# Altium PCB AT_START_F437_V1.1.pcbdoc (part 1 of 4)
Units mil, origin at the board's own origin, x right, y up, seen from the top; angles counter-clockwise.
Board outline 10746.75 x 3533.35 mil, 2 copper layers (Top Layer, Bottom Layer); 198 components, 235 nets, 885 pads, 1100 vias.
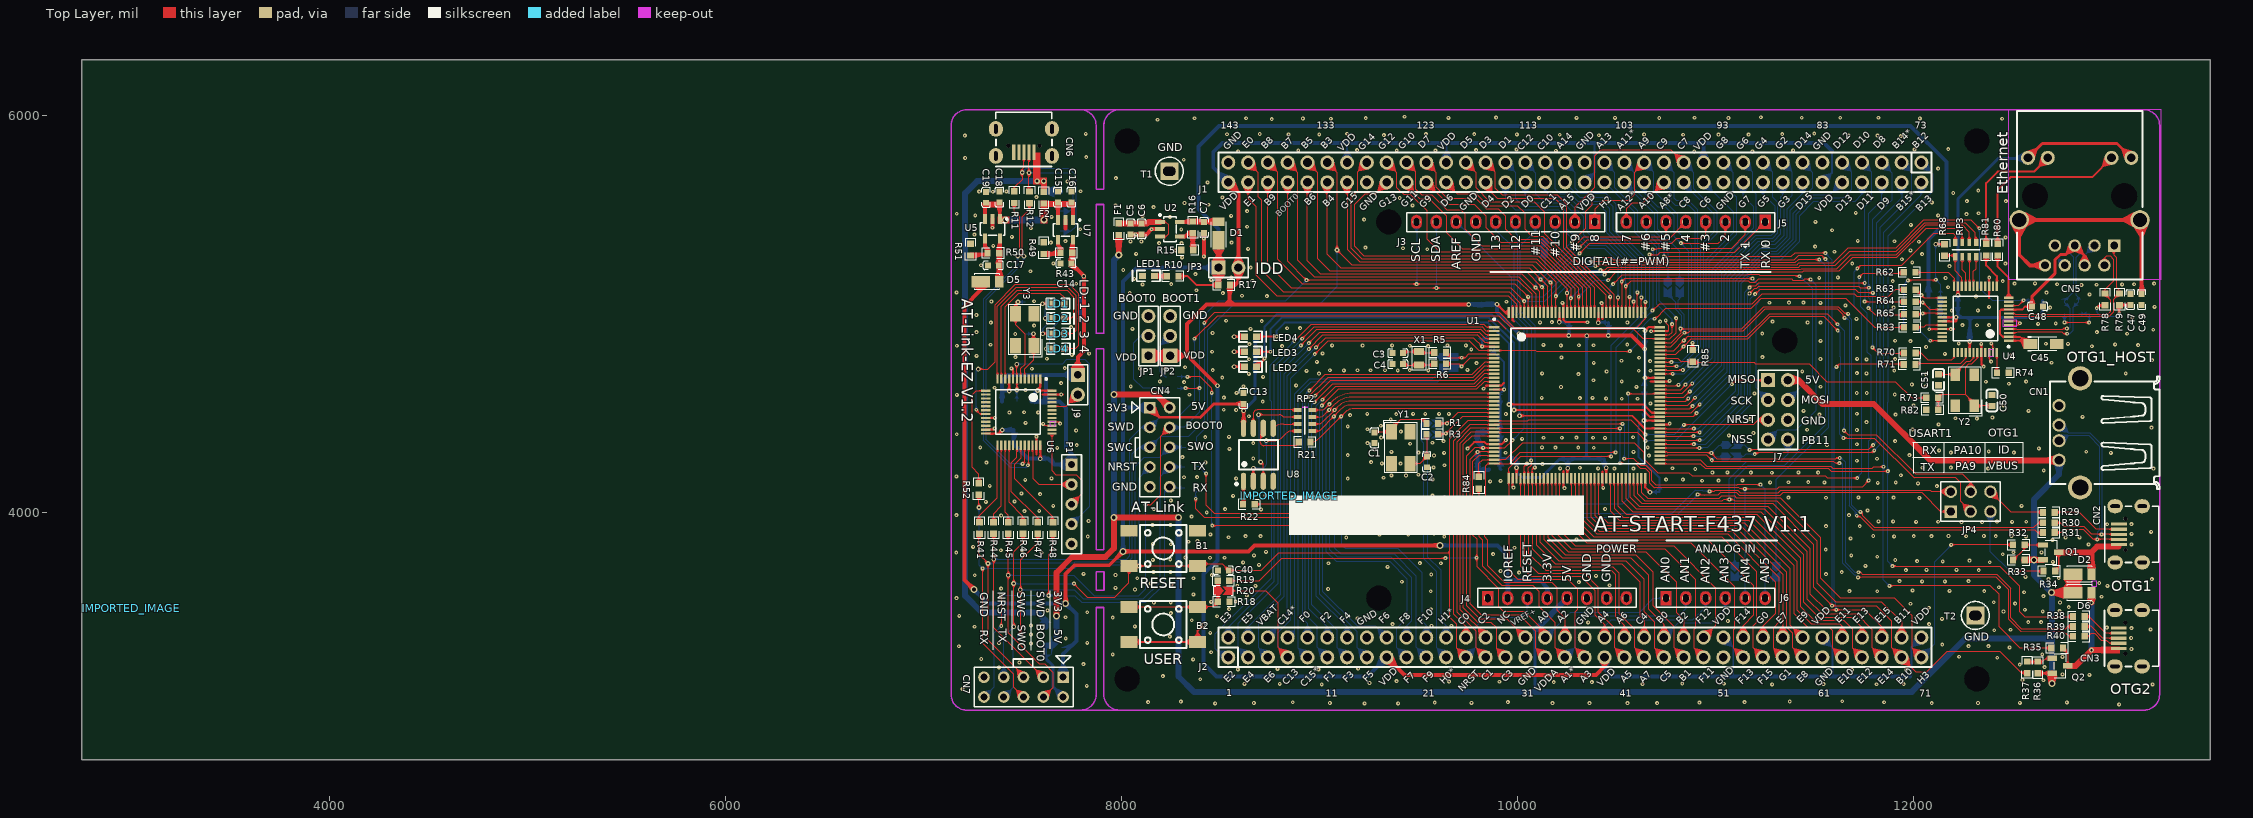
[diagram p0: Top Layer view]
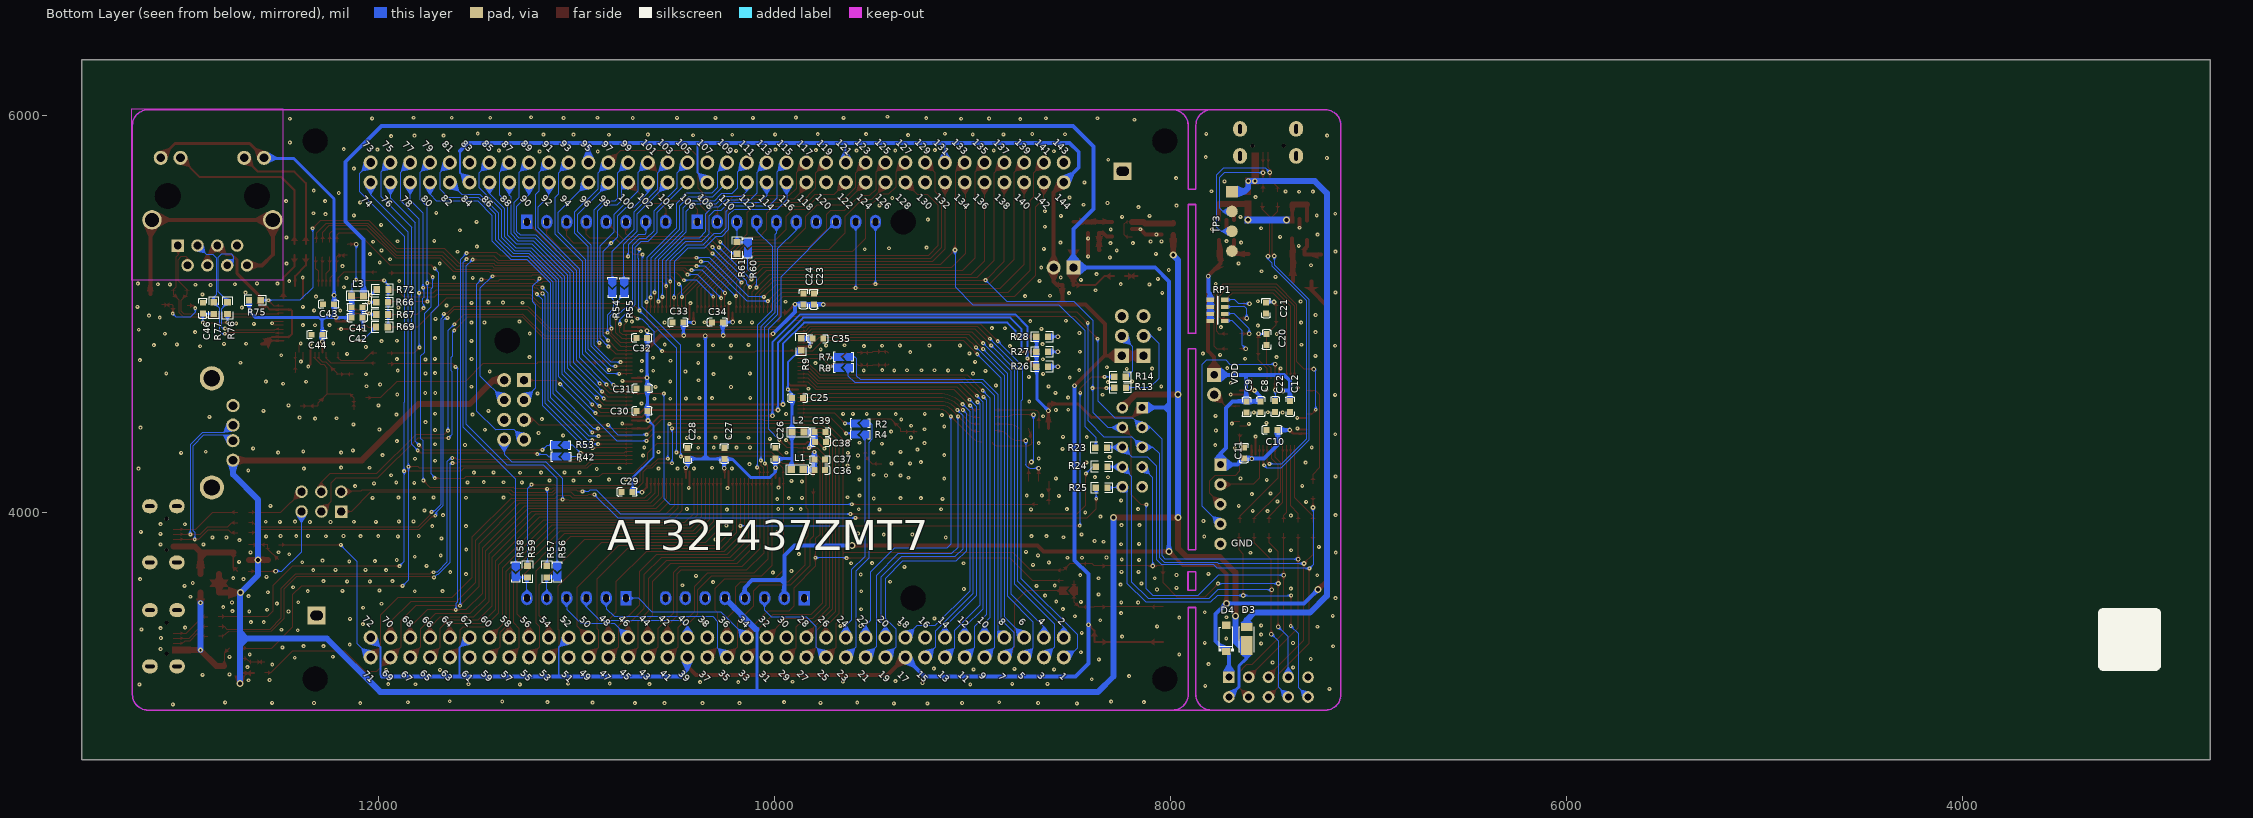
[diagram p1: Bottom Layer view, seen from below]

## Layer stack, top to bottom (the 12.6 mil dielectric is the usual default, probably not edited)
Top Layer: signal copper (thickness not stored)
Dielectric: dielectric 12.6, FR-4, Dk 4.8
Bottom Layer: signal copper (thickness not stored)

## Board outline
13496.75,2750 2750,2750 2750,6283.35 13496.75,6283.35
cut-out: 11412.34,4865.35 ccw(c11349.35,4865.35) 11286.36,4865.35 ccw(c11349.35,4865.35)
cut-out: 9412.34,5465.35 ccw(c9349.35,5465.35) 9286.36,5465.35 ccw(c9349.35,5465.35)
cut-out: 9362.34,3565.36 ccw(c9299.35,3565.36) 9236.36,3565.36 ccw(c9299.35,3565.36)
cut-out: 8090.92,5874.02 ccw(c8027.93,5874.02) 7964.94,5874.02 ccw(c8027.93,5874.02)
cut-out: 8090.92,3157.47 ccw(c8027.93,3157.47) 7964.94,3157.47 ccw(c8027.93,3157.47)
cut-out: 12382.26,3157.47 ccw(c12319.27,3157.47) 12256.28,3157.47 ccw(c12319.27,3157.47)
cut-out: 12382.26,5874.02 ccw(c12319.27,5874.02) 12256.28,5874.02 ccw(c12319.27,5874.02)

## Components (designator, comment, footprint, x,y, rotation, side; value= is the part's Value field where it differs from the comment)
B1 "贴片按键6*6*5 黑色" SW-SMD_4P-L6.0-W6.0-P4.50-LS9.0 8210.8,3816.36 r180 top
B2 "贴片按键6*6*5 红色" SW-SMD_4P-L6.0-W6.0-P4.50-LS9.0 8210.8,3432.36 r180 top
C1 "22pF" 0603_C-M 9277.75,4375.35 r270 top
C2 "22pF" 0603_C-M 9541.37,4253.71 r270 top
C3 "10pF" 0603_C-M 9394.6,4802.55 r180 top
C4 "10pF" 0603_C-M 9394.61,4747 r180 top
C5 "10uF" 0603_C-M 8045.76,5429 r90 top
C6 "0.1uF" 0603_C-M 8100.76,5429 r90 top
C7 "10uF" 0603_C-M 8415.75,5437.35 r90 top
C8 "4.7uF" 0603_C-M 7544.2,4531.56 r90 bottom
C9 "0.1uF" 0603_C-M 7616.2,4530.56 r90 bottom
C10 "0.1uF" 0603_C-M 7487.2,4414.56 r180 bottom
C11 "0.1uF" 0603_C-M 7629.2,4298.56 r270 bottom
C12 "0.1uF" 0603_C-M 7396.2,4532.56 r90 bottom
C13 "0.1uF" 0603_C-M 8615.73,4574.23 r270 top
C14 "10uF" 0603_C-M 7719.11,5255 r0 top
C15 "10uF" 0603_C-M 7678.2,5590.56 r270 top
C16 "0.1uF" 0603_C-M 7747.2,5590.56 r270 top
C17 "10uF" 0603_C-M 7352.2,5245.56 r0 top
C18 "10uF" 0603_C-M 7383.2,5590.56 r270 top
C19 "0.1uF" 0603_C-M 7316.2,5589.56 r270 top
C20 "22pF" 0603_C-M 7514.2,4870.56 r90 bottom
C21 "22pF" 0603_C-M 7517.2,5030.56 r270 bottom
C22 "0.1uF" 0603_C-M 7471.2,4532.56 r90 bottom
C23 "4.7uF" 0603_C-M 9800.75,5075.35 r270 bottom
C24 "0.1uF" 0603_C-M 9852.75,5076.35 r270 bottom
C25 "0.1uF" 0603_C-M 9882.75,4576.35 r0 bottom
C26 "0.1uF" 0603_C-M 9994.75,4297.35 r270 bottom
C27 "0.1uF" 0603_C-M 10252.75,4295.35 r270 bottom
C28 "0.1uF" 0603_C-M 10437.75,4296.35 r270 bottom
C29 "0.1uF" 0603_C-M 10743.75,4101.35 r180 bottom
C30 "0.1uF" 0603_C-M 10668.75,4510.35 r180 bottom
C31 "0.1uF" 0603_C-M 10667.75,4623.35 r180 bottom
C32 "0.1uF" 0603_C-M 10669.75,4879.35 r180 bottom
C33 "0.1uF" 0603_C-M 10486.75,4957.35 r180 bottom
C34 "0.1uF" 0603_C-M 10287.75,4958.35 r180 bottom
C35 "0.1uF" 0603_C-M 9780.75,4875.35 r0 bottom
C36 "1uF" 0603_C-M 9770.75,4212.35 r0 bottom
C37 "0.1uF" 0603_C-M 9770.75,4264.35 r0 bottom
C38 "0.1uF" 0603_C-M 9767.75,4354.35 r0 bottom
C39 "1uF" 0603_C-M 9768.75,4404.35 r0 bottom
C40 "0.1uF" 0603_C-M 8513.75,3705.35 r0 top
C41 "10uF" 0603_C-M 12106.75,5034.35 r0 bottom
C42 "0.1uF" 0603_C-M 12106.75,4982.35 r0 bottom
C43 "0.1uF" 0603_C-M 12250.75,5049.35 r180 bottom
C44 "0.1uF" 0603_C-M 12309.75,4895.35 r180 bottom
C45 "47uF" CAP-SMD_L3.2-W1.6-R-RD 12655.75,4849.35 r180 top
C46 "0.1uF" 0603_C-M 12886.04,5029.49 r270 bottom
C47 "0.1uF" 0603_C-M 13094.07,5073.23 r270 top
C48 "0.1uF" 0603_C-M 12625.75,5037.35 r0 top
C49 "0.1uF" 0603_C-M 13151.2,5073.23 r270 top
C50 "0603CG300J500NT" C0603 12395.11,4563.79 r90 top
C51 "0603CG300J500NT" C0603 12125.62,4668.2 r270 top
CN1 "JTJ-USB-AF-08" USB-A-TH__USB-AF-90 12787.14,4399.88 r90 top
CN2 "USB_micro B" USB_MIC_DIP 13036.55,3887.68 r0 top
CN3 "USB_micro B" USB_MIC_DIP 13035.76,3362.87 r0 top
CN4 "CON10A_0" HDR2X5 8142.77,4527.36 r270 top
CN5 "RJ45(TRJ201)" RJ45-TH_HR911105A 12837.8,5517.32 r180 top
CN6 "USB_micro B" USB_MIC_DIP 7506.75,5817.58 r90 top
CN7 "CON1" HDR2X5 7705,3165.97 r180 top
D1 "DFLS130L-7" POWERDI-123_L2.8-W1.8-LS3.7-RD 8489.75,5419.36 r90 top
D2 "DFLS130L-7" POWERDI-123_L2.8-W1.8-LS3.7-RD 12850.97,3686.74 r0 top
D3 "DFLS130L-7" POWERDI-123_L2.8-W1.8-LS3.7-RD 7615.25,3372.57 r90 bottom
D4 "SMF3.3A" SOD-123_L2.8-W1.8-LS3.7-RD 7718.2,3362.57 r90 bottom
D5 "DFLS130L-7" POWERDI-123_L2.8-W1.8-LS3.7-RD 7335.25,5163.56 r0 top
D6 "DFLS130L-7" POWERDI-123_L2.8-W1.8-LS3.7-RD 12850.97,3592.97 r0 top
F1 "SMD0603B050TF" R0603 7985.8,5428.97 r90 top
F2 "SMD0603B050TF" R0603 7607.2,5587.56 r270 top
IMPORTED_IMAGE "IMPORTED_IMAGE" IMPORTED_IMAGE 3000,3514.32 r0 top
IMPORTED_IMAGE "IMPORTED_IMAGE" IMPORTED_IMAGE 8845.96,4083.03 r0 top
J1 "HDR 2X36" HDR_2.54_2X36 10288.72,5715.04 r180 top
J2 "HDR 2X36" HDR_2.54_2X36 10288.72,3316.46 r0 top
J3 "CON10" "FEMALE HEADER 1X10" 9939.35,5465.35 r0 top
J4 "CON8" "FEMALE HEADER 1X8" 10199.35,3565.35 r0 top
J5 "CON8" "FEMALE HEADER 1X8" 10899.35,5465.35 r180 top
J6 "CON6" "FEMALE HEADER 1X6" 10999.35,3565.35 r0 top
J7 "Header 4X2" HDR2X4 11264.35,4665.94 r270 top
J9 "1X2P,Male,DIP_2.54" HDR1X2 7779,4692.97 r270 top
JP1 "Jumper 1x3P" "HEADER 1X3" 8135.76,4789.35 r90 top
JP2 "Jumper 1x3P" "HEADER 1X3" 8245.75,4789.35 r90 top
JP3 "Jumper 1x2P" "HEADER 1X2" 8489.75,5234.35 r0 top
JP4 "Header 3X2" HDR2X3 12187.48,4002.73 r0 top
L1 "0.5A,600Ω@100Mhz" 0603_L 9884.8,4214.36 r180 bottom
L2 "0.5A,600Ω@100Mhz" 0603_L 9880.8,4403.36 r180 bottom
L3 "0.5A,600Ω@100Mhz" 0603_L 12104.8,5091.36 r0 bottom
LD1 "RED" LED0603 7649.02,5051.81 r0 top
LD2 "GREEN" LED0603 7649.98,4977.72 r0 top
LD3 "BLUE" LED0603 7650.02,4900.81 r0 top
LD4 "YELLOW" LED0603 7649.98,4824.81 r0 top
LED1 "RED" LED0603 8165.76,5192.35 r180 top
LED2 "RED" LED0603 8620.59,4734.39 r0 top
LED3 "YELLOW" LED0603 8620.6,4809.37 r0 top
LED4 "GREEN" LED0603 8620.6,4885.67 r0 top
P1 "HDR-M-2.54_1x5" HDR-M-2.54_1X5 7747.7,4039.57 r270 top
Q1 "SI2301" SOT-23-3_L2.9-W1.3-P1.90-LS2.4-BR 12692.6,3796.36 r180 top
Q2 "SI2301" SOT-23-3_L2.9-W1.3-P1.90-LS2.4-BR 12738.7,3223.57 r180 top
R1 "0603WAF0000T5E" R0603 9569.75,4447.35 r0 top
R2 "NC" SB-PAD 9567.75,4447.35 r0 bottom
R3 "0603WAF0000T5E" R0603 9569.75,4393.35 r0 top
R4 "NC" SB-PAD 9567.75,4391.35 r0 bottom
R5 "0603WAF0000T5E" R0603 9608.75,4805.31 r0 top
R6 "0603WAF0000T5E" R0603 9608.75,4748.57 r0 top
R7 "NC" SB-PAD 9651.75,4783.35 r0 bottom
R8 "NC" SB-PAD 9651.75,4729.35 r0 bottom
R9 "0603WAF0000T5E" R0603 9864.75,4847.35 r270 bottom
R10 "0603WAF1001T5E" R0603 8257.8,5191.36 r180 top
R11 "0603WAF0000T5E" R0603 7458.2,5590.56 r270 top
R12 "0603WAF0000T5E" R0603 7535.2,5589.56 r270 top
R13 "0603WAF1002T5E" R0603 8253.75,4627.35 r0 bottom
R14 "0603WAF1002T5E" R0603 8254.75,4683.35 r0 bottom
R15 "0603WAF1502T5E" R0603 8331.75,5323.35 r180 top
R16 "0603WAF5102T5E" R0603 8359.75,5437.35 r90 top
R17 "0603WAF0000T5E" R0603 8517.75,5146.35 r0 top
R18 "0603WAF1003T5E" R0603 8515.75,3547.35 r180 top
R19 "0603WAF0000T5E" R0603 8514.75,3653.35 r0 top
R20 "NC" SB-PAD 8514.75,3602.35 r0 top
R21 "0603WAF330JT5E" R0603 8924.73,4353.23 r180 top
R22 "0603WAF330JT5E" R0603 8643.05,4039.37 r180 top
R23 "0603WAF4700T5E" R0603 8349.8,4325.36 r0 bottom
R24 "0603WAF4700T5E" R0603 8347.8,4229.36 r0 bottom
R25 "0603WAF4700T5E" R0603 8347.2,4122.47 r0 bottom
R26 "0603WAF1001T5E" R0603 8647.4,4734.39 r180 bottom
R27 "0603WAF1001T5E" R0603 8647.4,4809.38 r180 bottom
R28 "0603WAF1001T5E" R0603 8647.4,4885.68 r180 bottom
R29 "0603WAF1001T5E" R0603 12682.57,3998.35 r0 top
R30 "0603WAF220JT5E" R0603 12682.57,3946.35 r0 top
R31 "0603WAF220JT5E" R0603 12682.57,3896.35 r0 top
R32 "0603WAF4700T5E" R0603 12530.57,3834.35 r0 top
R33 "0603WAF1002T5E" R0603 12530.57,3758.35 r0 top
R34 "0603WAF1002T5E" R0603 12684.6,3702.36 r0 top
R35 "0603WAF1002T5E" R0603 12724.7,3313.57 r0 top
R36 "0603WAF1002T5E" R0603 12626.72,3215.58 r270 top
R37 "0603WAF4700T5E" R0603 12572.72,3215.58 r90 top
R38 "0603WAF1001T5E" R0603 12834.51,3472.35 r0 top
R39 "0603WAF220JT5E" R0603 12834.51,3422.35 r0 top
R40 "0603WAF220JT5E" R0603 12834.51,3372.35 r0 top
R41 "0603WAF330JT5E" R0603 7283.2,3919.56 r90 top
R42 "NC" SB-PAD 11078.75,4280.35 r0 bottom
R43 "0603WAF4702T5E" R0603 7721.2,5309.93 r0 top
R44 "0603WAF330JT5E" R0603 7353.2,3919.57 r90 top
R45 "0603WAF330JT5E" R0603 7428.2,3919.57 r90 top
R46 "0603WAF330JT5E" R0603 7502.2,3919.56 r90 top
R47 "0603WAF330JT5E" R0603 7577.2,3919.57 r90 top
R48 "0603WAF330JT5E" R0603 7653.2,3919.56 r90 top
R49 "0603WAF1502T5E" R0603 7607.2,5332.56 r90 top
R50 "0603WAF5102T5E" R0603 7352.2,5307.56 r0 top
R51 "0603WAF1502T5E" R0603 7237.2,5325.56 r90 top
R52 "0603WAF330JT5E" R0603 7278.2,4116.56 r90 top
R53 "NC" SB-PAD 11080.75,4338.35 r0 bottom
R54 "NC" SB-PAD 10818.94,5134.93 r270 bottom
R55 "NC" SB-PAD 10758.57,5134.14 r270 bottom
R56 "NC" SB-PAD 11095.75,3699.35 r270 bottom
R57 "0603WAF0000T5E" R0603 11149.75,3699.35 r270 bottom
R58 "NC" SB-PAD 11306.49,3698.56 r270 bottom
R59 "0603WAF0000T5E" R0603 11246.6,3699.35 r270 bottom
R60 "NC" SB-PAD 10133.39,5334.56 r270 bottom
R61 "0603WAF0000T5E" R0603 10188.75,5334.35 r90 bottom
R62 "0603WAF330JT5E" R0603 11979.75,5211.35 r0 top
R63 "0603WAF330JT5E" R0603 11980.63,5123.27 r0 top
R64 "0603WAF330JT5E" R0603 11980.63,5062.2 r0 top
R65 "0603WAF330JT5E" R0603 11980.63,4998.37 r0 top
R66 "0603WAF4701T5E" R0603 11980.4,5059.71 r0 bottom
R67 "0603WAF4701T5E" R0603 11981.02,4997.97 r0 bottom
R68 "0603WAF4701T5E" R0603 12155.75,5323.35 r270 top
R69 "0603WAF4701T5E" R0603 11981.41,4934.54 r0 bottom
R70 "0603WAF330JT5E" R0603 11980.4,4803.71 r0 top
R71 "0603WAF330JT5E" R0603 11979.75,4745.35 r0 top
R72 "0603WAF1501T5E" R0603 11978.66,5123.66 r180 bottom
R73 "0603WAF330JT5E" R0603 12093.7,4577.58 r0 top
R74 "0603WAF6801T5E" R0603 12449.75,4703.35 r180 top
R75 "0603WAF4701T5E" R0603 12622.8,5069.36 r0 bottom
R76 "0603WAF499JT5E" R0603 12761.75,5029.35 r90 bottom
R77 "0603WAF499JT5E" R0603 12831.27,5030.28 r90 bottom
R78 "0603WAF499JT5E" R0603 12965.63,5073.62 r90 top
R79 "0603WAF499JT5E" R0603 13038.91,5073.62 r90 top
R80 "0603WAF4700T5E" R0603 12423.75,5325.35 r270 top
R81 "0603WAF4700T5E" R0603 12365.75,5325.35 r270 top
R82 "0603WAF1003T5E" R0603 12093.7,4516.51 r180 top
R83 "0603WAF330JT5E" R0603 11980.63,4932.96 r0 top
R84 "0603WAF0000T5E" R0603 9804.17,4148.12 r90 top
R85 "0603WAF0000T5E" R0603 10884.91,4788.37 r270 top
RP1 "1K" 0603*4,8P4R 7798.2,5071.56 r270 bottom
RP2 "33R" 0603*4,8P4R 8962.73,4409.23 r90 top
RP3 "33R" 0603*4,8P4R 12315.75,5361.35 r180 top
T1 "TESTPOINT TP-5006" TESTHOOK 8241.01,5721.13 r0 top
T2 "TESTPOINT TP-5006" TESTHOOK 12311.19,3477.92 r0 top
TP3 "1X4P_2.54F" "HDR1X4 - TOP" 7689.55,5618.02 r90 bottom
U1 "AT32F437ZMT7" LQFP144_20*20 10299.74,4589.37 r0 top
U2 "RT9080N-08GJ5" SOT-23-5 8258.75,5365.35 r0 top
U4 "DM9162EP" LQFP48_7*7 12311.75,4973.35 r180 top
U5 "RT9080N-08GJ5" SOT-23-5 7285.2,5415.56 r270 top
U6 "AT32F403CGT6" "LQFP48 - 2" 7589.72,4672.02 r270 top
U7 "RT9080N-08GJ5" SOT-23-5 7653.98,5409.91 r270 top
U8 "EN25QH128A-104HIP" SOIC-8_208MIL 8690.7,4289.16 r0 top
X1 "32.768KHz" FC-12M_L2.0-W1.2 9501.97,4776.55 r90 top
Y1 "8MHz" OSC-SMD_4P-L5.0-W3.2-BL 9409.8,4325.36 r270 top
Y2 "X503225MSB4SI" CRYSTAL-SMD_4P-L5.0-W3.2-BL 12257.61,4614.61 r90 top
Y3 "8MHz" OSC-SMD_4P-L5.0-W3.2-BL 7510.6,4920.97 r90 top

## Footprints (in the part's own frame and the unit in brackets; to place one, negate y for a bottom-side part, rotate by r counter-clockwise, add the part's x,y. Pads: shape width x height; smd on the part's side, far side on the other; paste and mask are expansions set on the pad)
0603*4,8P4R [mm]
  rect 0.55x0.95 smd: 1(0,0) 4(2.7,0) 5(2.7,1.85) 8(0,1.85)
  rect 0.5x0.95 smd: 2(0.9,0) 3(1.8,0) 6(1.8,1.85) 7(0.9,1.85)
  silkscreen extent -0.43,0.94 3.1,0.94
0603_C-M [mil]
  rect 30x30 smd: 1(27.5,0) 2(-27.5,0)
  silkscreen extent -50,-21 50,21
0603_L [mm]
  rect 0.93x0.9 smd: 1(-0.77,0) 2(0.77,0)
  silkscreen extent -1.4,-0.64 1.4,0.64
C0603 [mm]
  rect 0.8x0.9 smd: 1(-0.7,0) 2(0.7,0)
  silkscreen extent -1.41,-0.71 1.39,0.72
CAP-SMD_L3.2-W1.6-R-RD [mil]
  rect 69.19x51.02 smd: 1(66.38,0) 2(-66.39,0)
  silkscreen extent -66,-37 81,37
CRYSTAL-SMD_4P-L5.0-W3.2-BL [mm]
  rect 1.6x1.2 smd: 1(-2,-1.2) 2(2,-1.2) 3(2,1.2) 4(-2,1.2)
  silkscreen extent -3.26,-2.26 3.03,2.03
FC-12M_L2.0-W1.2 [mm]
  rect 0.925x1.3 smd: 1(-0.863,0) 2(0.863,0)
  silkscreen extent -1.55,-0.88 1.55,0.88
"FEMALE HEADER 1X6" [mm]
  oval 1x0.7 hole 0.7 slot 1 at 90 deg: 1(-6.35,0) 2(-3.81,0) 3(-1.27,0) 4(1.27,0) 5(3.81,0) 6(6.35,0)
  Top Layer region: 7.05,-0.2 6.956,-0.55 6.7,-0.806 6.35,-0.9 6,-0.806 5.744,-0.55 5.65,-0.2 5.65,0.2 5.744,0.55 6,0.806 6.35,0.9 6.7,0.806 6.956,0.55 7.05,0.2
  Top Layer region: 4.51,-0.2 4.416,-0.55 4.16,-0.806 3.81,-0.9 3.46,-0.806 3.204,-0.55 3.11,-0.2 3.11,0.2 3.204,0.55 3.46,0.806 3.81,0.9 4.16,0.806 4.416,0.55 4.51,0.2
  Top Layer region: 1.97,-0.2 1.876,-0.55 1.62,-0.806 1.27,-0.9 0.92,-0.806 0.664,-0.55 0.57,-0.2 0.57,0.2 0.664,0.55 0.92,0.806 1.27,0.9 1.62,0.806 1.876,0.55 1.97,0.2
  Top Layer region: -0.57,-0.2 -0.664,-0.55 -0.92,-0.806 -1.27,-0.9 -1.62,-0.806 -1.876,-0.55 -1.97,-0.2 -1.97,0.2 -1.876,0.55 -1.62,0.806 -1.27,0.9 -0.92,0.806 -0.664,0.55 -0.57,0.2
  Top Layer region: -3.11,-0.2 -3.204,-0.55 -3.46,-0.806 -3.81,-0.9 -4.16,-0.806 -4.416,-0.55 -4.51,-0.2 -4.51,0.2 -4.416,0.55 -4.16,0.806 -3.81,0.9 -3.46,0.806 -3.204,0.55 -3.11,0.2
  Top Layer region: -7.05,0.9 -5.65,0.9 -5.65,-0.9 -7.05,-0.9
  Bottom Layer region: 7.05,-0.2 6.956,-0.55 6.7,-0.806 6.35,-0.9 6,-0.806 5.744,-0.55 5.65,-0.2 5.65,0.2 5.744,0.55 6,0.806 6.35,0.9 6.7,0.806 6.956,0.55 7.05,0.2
  Bottom Layer region: 4.51,-0.2 4.416,-0.55 4.16,-0.806 3.81,-0.9 3.46,-0.806 3.204,-0.55 3.11,-0.2 3.11,0.2 3.204,0.55 3.46,0.806 3.81,0.9 4.16,0.806 4.416,0.55 4.51,0.2
  Bottom Layer region: 1.97,-0.2 1.876,-0.55 1.62,-0.806 1.27,-0.9 0.92,-0.806 0.664,-0.55 0.57,-0.2 0.57,0.2 0.664,0.55 0.92,0.806 1.27,0.9 1.62,0.806 1.876,0.55 1.97,0.2
  Bottom Layer region: -0.57,-0.2 -0.664,-0.55 -0.92,-0.806 -1.27,-0.9 -1.62,-0.806 -1.876,-0.55 -1.97,-0.2 -1.97,0.2 -1.876,0.55 -1.62,0.806 -1.27,0.9 -0.92,0.806 -0.664,0.55 -0.57,0.2
  Bottom Layer region: -3.11,-0.2 -3.204,-0.55 -3.46,-0.806 -3.81,-0.9 -4.16,-0.806 -4.416,-0.55 -4.51,-0.2 -4.51,0.2 -4.416,0.55 -4.16,0.806 -3.81,0.9 -3.46,0.806 -3.204,0.55 -3.11,0.2
  Bottom Layer region: -7.05,0.9 -5.65,0.9 -5.65,-0.9 -7.05,-0.9
  Multi-Layer region: 7.05,-0.2 6.956,-0.55 6.7,-0.806 6.35,-0.9 6,-0.806 5.744,-0.55 5.65,-0.2 5.65,0.2 5.744,0.55 6,0.806 6.35,0.9 6.7,0.806 6.956,0.55 7.05,0.2
  Multi-Layer region: 4.51,-0.2 4.416,-0.55 4.16,-0.806 3.81,-0.9 3.46,-0.806 3.204,-0.55 3.11,-0.2 3.11,0.2 3.204,0.55 3.46,0.806 3.81,0.9 4.16,0.806 4.416,0.55 4.51,0.2
  Multi-Layer region: 1.97,-0.2 1.876,-0.55 1.62,-0.806 1.27,-0.9 0.92,-0.806 0.664,-0.55 0.57,-0.2 0.57,0.2 0.664,0.55 0.92,0.806 1.27,0.9 1.62,0.806 1.876,0.55 1.97,0.2
  Multi-Layer region: -0.57,-0.2 -0.664,-0.55 -0.92,-0.806 -1.27,-0.9 -1.62,-0.806 -1.876,-0.55 -1.97,-0.2 -1.97,0.2 -1.876,0.55 -1.62,0.806 -1.27,0.9 -0.92,0.806 -0.664,0.55 -0.57,0.2
  Multi-Layer region: -3.11,-0.2 -3.204,-0.55 -3.46,-0.806 -3.81,-0.9 -4.16,-0.806 -4.416,-0.55 -4.51,-0.2 -4.51,0.2 -4.416,0.55 -4.16,0.806 -3.81,0.9 -3.46,0.806 -3.204,0.55 -3.11,0.2
  Multi-Layer region: -7.05,0.9 -5.65,0.9 -5.65,-0.9 -7.05,-0.9
  silkscreen extent -7.62,-1.17 7.62,1.27
"FEMALE HEADER 1X8" [mm]
  oval 1x0.7 hole 0.7 slot 1 at 90 deg: 1(-8.89,0) 2(-6.35,0) 3(-3.81,0) 4(-1.27,0) 5(1.27,0) 6(3.81,0) 7(6.35,0) 8(8.89,0)
  Top Layer region: 9.59,-0.2 9.496,-0.55 9.24,-0.806 8.89,-0.9 8.54,-0.806 8.284,-0.55 8.19,-0.2 8.19,0.2 8.284,0.55 8.54,0.806 8.89,0.9 9.24,0.806 9.496,0.55 9.59,0.2
  Top Layer region: 7.05,-0.2 6.956,-0.55 6.7,-0.806 6.35,-0.9 6,-0.806 5.744,-0.55 5.65,-0.2 5.65,0.2 5.744,0.55 6,0.806 6.35,0.9 6.7,0.806 6.956,0.55 7.05,0.2
  Top Layer region: 4.51,-0.2 4.416,-0.55 4.16,-0.806 3.81,-0.9 3.46,-0.806 3.204,-0.55 3.11,-0.2 3.11,0.2 3.204,0.55 3.46,0.806 3.81,0.9 4.16,0.806 4.416,0.55 4.51,0.2
  Top Layer region: 1.97,-0.2 1.876,-0.55 1.62,-0.806 1.27,-0.9 0.92,-0.806 0.664,-0.55 0.57,-0.2 0.57,0.2 0.664,0.55 0.92,0.806 1.27,0.9 1.62,0.806 1.876,0.55 1.97,0.2
  Top Layer region: -0.57,-0.2 -0.664,-0.55 -0.92,-0.806 -1.27,-0.9 -1.62,-0.806 -1.876,-0.55 -1.97,-0.2 -1.97,0.2 -1.876,0.55 -1.62,0.806 -1.27,0.9 -0.92,0.806 -0.664,0.55 -0.57,0.2
  Top Layer region: -3.11,-0.2 -3.204,-0.55 -3.46,-0.806 -3.81,-0.9 -4.16,-0.806 -4.416,-0.55 -4.51,-0.2 -4.51,0.2 -4.416,0.55 -4.16,0.806 -3.81,0.9 -3.46,0.806 -3.204,0.55 -3.11,0.2
  Top Layer region: -5.65,-0.2 -5.744,-0.55 -6,-0.806 -6.35,-0.9 -6.7,-0.806 -6.956,-0.55 -7.05,-0.2 -7.05,0.2 -6.956,0.55 -6.7,0.806 -6.35,0.9 -6,0.806 -5.744,0.55 -5.65,0.2
  Top Layer region: -9.59,0.9 -8.19,0.9 -8.19,-0.9 -9.59,-0.9
  Bottom Layer region: 9.59,-0.2 9.496,-0.55 9.24,-0.806 8.89,-0.9 8.54,-0.806 8.284,-0.55 8.19,-0.2 8.19,0.2 8.284,0.55 8.54,0.806 8.89,0.9 9.24,0.806 9.496,0.55 9.59,0.2
  Bottom Layer region: 7.05,-0.2 6.956,-0.55 6.7,-0.806 6.35,-0.9 6,-0.806 5.744,-0.55 5.65,-0.2 5.65,0.2 5.744,0.55 6,0.806 6.35,0.9 6.7,0.806 6.956,0.55 7.05,0.2
  Bottom Layer region: 4.51,-0.2 4.416,-0.55 4.16,-0.806 3.81,-0.9 3.46,-0.806 3.204,-0.55 3.11,-0.2 3.11,0.2 3.204,0.55 3.46,0.806 3.81,0.9 4.16,0.806 4.416,0.55 4.51,0.2
  Bottom Layer region: 1.97,-0.2 1.876,-0.55 1.62,-0.806 1.27,-0.9 0.92,-0.806 0.664,-0.55 0.57,-0.2 0.57,0.2 0.664,0.55 0.92,0.806 1.27,0.9 1.62,0.806 1.876,0.55 1.97,0.2
  Bottom Layer region: -0.57,-0.2 -0.664,-0.55 -0.92,-0.806 -1.27,-0.9 -1.62,-0.806 -1.876,-0.55 -1.97,-0.2 -1.97,0.2 -1.876,0.55 -1.62,0.806 -1.27,0.9 -0.92,0.806 -0.664,0.55 -0.57,0.2
  Bottom Layer region: -3.11,-0.2 -3.204,-0.55 -3.46,-0.806 -3.81,-0.9 -4.16,-0.806 -4.416,-0.55 -4.51,-0.2 -4.51,0.2 -4.416,0.55 -4.16,0.806 -3.81,0.9 -3.46,0.806 -3.204,0.55 -3.11,0.2
  Bottom Layer region: -5.65,-0.2 -5.744,-0.55 -6,-0.806 -6.35,-0.9 -6.7,-0.806 -6.956,-0.55 -7.05,-0.2 -7.05,0.2 -6.956,0.55 -6.7,0.806 -6.35,0.9 -6,0.806 -5.744,0.55 -5.65,0.2
  Bottom Layer region: -9.59,0.9 -8.19,0.9 -8.19,-0.9 -9.59,-0.9
  Multi-Layer region: 9.59,-0.2 9.496,-0.55 9.24,-0.806 8.89,-0.9 8.54,-0.806 8.284,-0.55 8.19,-0.2 8.19,0.2 8.284,0.55 8.54,0.806 8.89,0.9 9.24,0.806 9.496,0.55 9.59,0.2
  Multi-Layer region: 7.05,-0.2 6.956,-0.55 6.7,-0.806 6.35,-0.9 6,-0.806 5.744,-0.55 5.65,-0.2 5.65,0.2 5.744,0.55 6,0.806 6.35,0.9 6.7,0.806 6.956,0.55 7.05,0.2
  Multi-Layer region: 4.51,-0.2 4.416,-0.55 4.16,-0.806 3.81,-0.9 3.46,-0.806 3.204,-0.55 3.11,-0.2 3.11,0.2 3.204,0.55 3.46,0.806 3.81,0.9 4.16,0.806 4.416,0.55 4.51,0.2
  Multi-Layer region: 1.97,-0.2 1.876,-0.55 1.62,-0.806 1.27,-0.9 0.92,-0.806 0.664,-0.55 0.57,-0.2 0.57,0.2 0.664,0.55 0.92,0.806 1.27,0.9 1.62,0.806 1.876,0.55 1.97,0.2
  Multi-Layer region: -0.57,-0.2 -0.664,-0.55 -0.92,-0.806 -1.27,-0.9 -1.62,-0.806 -1.876,-0.55 -1.97,-0.2 -1.97,0.2 -1.876,0.55 -1.62,0.806 -1.27,0.9 -0.92,0.806 -0.664,0.55 -0.57,0.2
  Multi-Layer region: -3.11,-0.2 -3.204,-0.55 -3.46,-0.806 -3.81,-0.9 -4.16,-0.806 -4.416,-0.55 -4.51,-0.2 -4.51,0.2 -4.416,0.55 -4.16,0.806 -3.81,0.9 -3.46,0.806 -3.204,0.55 -3.11,0.2
  Multi-Layer region: -5.65,-0.2 -5.744,-0.55 -6,-0.806 -6.35,-0.9 -6.7,-0.806 -6.956,-0.55 -7.05,-0.2 -7.05,0.2 -6.956,0.55 -6.7,0.806 -6.35,0.9 -6,0.806 -5.744,0.55 -5.65,0.2
  Multi-Layer region: -9.59,0.9 -8.19,0.9 -8.19,-0.9 -9.59,-0.9
  silkscreen extent -10.16,-1.17 10.16,1.27
"FEMALE HEADER 1X10" [mm]
  oval 1x0.7 hole 0.7 slot 1 at 90 deg: 1(11.43,0) 2(8.89,0) 3(6.35,0) 4(3.81,0) 5(1.27,0) 6(-1.27,0) 7(-3.81,0) 8(-6.35,0) 9(-8.89,0) 10(-11.43,0)
  Top Layer region: -12.13,0.2 -12.036,0.55 -11.78,0.806 -11.43,0.9 -11.08,0.806 -10.824,0.55 -10.73,0.2 -10.73,-0.2 -10.824,-0.55 -11.08,-0.806 -11.43,-0.9 -11.78,-0.806 -12.036,-0.55 -12.13,-0.2
  Top Layer region: -9.59,0.2 -9.496,0.55 -9.24,0.806 -8.89,0.9 -8.54,0.806 -8.284,0.55 -8.19,0.2 -8.19,-0.2 -8.284,-0.55 -8.54,-0.806 -8.89,-0.9 -9.24,-0.806 -9.496,-0.55 -9.59,-0.2
  Top Layer region: -7.05,0.2 -6.956,0.55 -6.7,0.806 -6.35,0.9 -6,0.806 -5.744,0.55 -5.65,0.2 -5.65,-0.2 -5.744,-0.55 -6,-0.806 -6.35,-0.9 -6.7,-0.806 -6.956,-0.55 -7.05,-0.2
  Top Layer region: -4.51,0.2 -4.416,0.55 -4.16,0.806 -3.81,0.9 -3.46,0.806 -3.204,0.55 -3.11,0.2 -3.11,-0.2 -3.204,-0.55 -3.46,-0.806 -3.81,-0.9 -4.16,-0.806 -4.416,-0.55 -4.51,-0.2
  Top Layer region: -1.97,0.2 -1.876,0.55 -1.62,0.806 -1.27,0.9 -0.92,0.806 -0.664,0.55 -0.57,0.2 -0.57,-0.2 -0.664,-0.55 -0.92,-0.806 -1.27,-0.9 -1.62,-0.806 -1.876,-0.55 -1.97,-0.2
  Top Layer region: 0.57,0.2 0.664,0.55 0.92,0.806 1.27,0.9 1.62,0.806 1.876,0.55 1.97,0.2 1.97,-0.2 1.876,-0.55 1.62,-0.806 1.27,-0.9 0.92,-0.806 0.664,-0.55 0.57,-0.2
  Top Layer region: 3.11,0.2 3.204,0.55 3.46,0.806 3.81,0.9 4.16,0.806 4.416,0.55 4.51,0.2 4.51,-0.2 4.416,-0.55 4.16,-0.806 3.81,-0.9 3.46,-0.806 3.204,-0.55 3.11,-0.2
  Top Layer region: 5.65,0.2 5.744,0.55 6,0.806 6.35,0.9 6.7,0.806 6.956,0.55 7.05,0.2 7.05,-0.2 6.956,-0.55 6.7,-0.806 6.35,-0.9 6,-0.806 5.744,-0.55 5.65,-0.2
  Top Layer region: 8.19,0.2 8.284,0.55 8.54,0.806 8.89,0.9 9.24,0.806 9.496,0.55 9.59,0.2 9.59,-0.2 9.496,-0.55 9.24,-0.806 8.89,-0.9 8.54,-0.806 8.284,-0.55 8.19,-0.2
  Top Layer region: 12.13,-0.9 10.73,-0.9 10.73,0.9 12.13,0.9
  Bottom Layer region: -12.13,0.2 -12.036,0.55 -11.78,0.806 -11.43,0.9 -11.08,0.806 -10.824,0.55 -10.73,0.2 -10.73,-0.2 -10.824,-0.55 -11.08,-0.806 -11.43,-0.9 -11.78,-0.806 -12.036,-0.55 -12.13,-0.2
  Bottom Layer region: -9.59,0.2 -9.496,0.55 -9.24,0.806 -8.89,0.9 -8.54,0.806 -8.284,0.55 -8.19,0.2 -8.19,-0.2 -8.284,-0.55 -8.54,-0.806 -8.89,-0.9 -9.24,-0.806 -9.496,-0.55 -9.59,-0.2
  Bottom Layer region: -7.05,0.2 -6.956,0.55 -6.7,0.806 -6.35,0.9 -6,0.806 -5.744,0.55 -5.65,0.2 -5.65,-0.2 -5.744,-0.55 -6,-0.806 -6.35,-0.9 -6.7,-0.806 -6.956,-0.55 -7.05,-0.2
  Bottom Layer region: -4.51,0.2 -4.416,0.55 -4.16,0.806 -3.81,0.9 -3.46,0.806 -3.204,0.55 -3.11,0.2 -3.11,-0.2 -3.204,-0.55 -3.46,-0.806 -3.81,-0.9 -4.16,-0.806 -4.416,-0.55 -4.51,-0.2
  Bottom Layer region: -1.97,0.2 -1.876,0.55 -1.62,0.806 -1.27,0.9 -0.92,0.806 -0.664,0.55 -0.57,0.2 -0.57,-0.2 -0.664,-0.55 -0.92,-0.806 -1.27,-0.9 -1.62,-0.806 -1.876,-0.55 -1.97,-0.2
  Bottom Layer region: 0.57,0.2 0.664,0.55 0.92,0.806 1.27,0.9 1.62,0.806 1.876,0.55 1.97,0.2 1.97,-0.2 1.876,-0.55 1.62,-0.806 1.27,-0.9 0.92,-0.806 0.664,-0.55 0.57,-0.2
  Bottom Layer region: 3.11,0.2 3.204,0.55 3.46,0.806 3.81,0.9 4.16,0.806 4.416,0.55 4.51,0.2 4.51,-0.2 4.416,-0.55 4.16,-0.806 3.81,-0.9 3.46,-0.806 3.204,-0.55 3.11,-0.2
  Bottom Layer region: 5.65,0.2 5.744,0.55 6,0.806 6.35,0.9 6.7,0.806 6.956,0.55 7.05,0.2 7.05,-0.2 6.956,-0.55 6.7,-0.806 6.35,-0.9 6,-0.806 5.744,-0.55 5.65,-0.2
  Bottom Layer region: 8.19,0.2 8.284,0.55 8.54,0.806 8.89,0.9 9.24,0.806 9.496,0.55 9.59,0.2 9.59,-0.2 9.496,-0.55 9.24,-0.806 8.89,-0.9 8.54,-0.806 8.284,-0.55 8.19,-0.2
  Bottom Layer region: 12.13,-0.9 10.73,-0.9 10.73,0.9 12.13,0.9
  Multi-Layer region: -12.13,0.2 -12.036,0.55 -11.78,0.806 -11.43,0.9 -11.08,0.806 -10.824,0.55 -10.73,0.2 -10.73,-0.2 -10.824,-0.55 -11.08,-0.806 -11.43,-0.9 -11.78,-0.806 -12.036,-0.55 -12.13,-0.2
  Multi-Layer region: -9.59,0.2 -9.496,0.55 -9.24,0.806 -8.89,0.9 -8.54,0.806 -8.284,0.55 -8.19,0.2 -8.19,-0.2 -8.284,-0.55 -8.54,-0.806 -8.89,-0.9 -9.24,-0.806 -9.496,-0.55 -9.59,-0.2
  Multi-Layer region: -7.05,0.2 -6.956,0.55 -6.7,0.806 -6.35,0.9 -6,0.806 -5.744,0.55 -5.65,0.2 -5.65,-0.2 -5.744,-0.55 -6,-0.806 -6.35,-0.9 -6.7,-0.806 -6.956,-0.55 -7.05,-0.2
  Multi-Layer region: -4.51,0.2 -4.416,0.55 -4.16,0.806 -3.81,0.9 -3.46,0.806 -3.204,0.55 -3.11,0.2 -3.11,-0.2 -3.204,-0.55 -3.46,-0.806 -3.81,-0.9 -4.16,-0.806 -4.416,-0.55 -4.51,-0.2
  Multi-Layer region: -1.97,0.2 -1.876,0.55 -1.62,0.806 -1.27,0.9 -0.92,0.806 -0.664,0.55 -0.57,0.2 -0.57,-0.2 -0.664,-0.55 -0.92,-0.806 -1.27,-0.9 -1.62,-0.806 -1.876,-0.55 -1.97,-0.2
  Multi-Layer region: 0.57,0.2 0.664,0.55 0.92,0.806 1.27,0.9 1.62,0.806 1.876,0.55 1.97,0.2 1.97,-0.2 1.876,-0.55 1.62,-0.806 1.27,-0.9 0.92,-0.806 0.664,-0.55 0.57,-0.2
  Multi-Layer region: 3.11,0.2 3.204,0.55 3.46,0.806 3.81,0.9 4.16,0.806 4.416,0.55 4.51,0.2 4.51,-0.2 4.416,-0.55 4.16,-0.806 3.81,-0.9 3.46,-0.806 3.204,-0.55 3.11,-0.2
  Multi-Layer region: 5.65,0.2 5.744,0.55 6,0.806 6.35,0.9 6.7,0.806 6.956,0.55 7.05,0.2 7.05,-0.2 6.956,-0.55 6.7,-0.806 6.35,-0.9 6,-0.806 5.744,-0.55 5.65,-0.2
  Multi-Layer region: 8.19,0.2 8.284,0.55 8.54,0.806 8.89,0.9 9.24,0.806 9.496,0.55 9.59,0.2 9.59,-0.2 9.496,-0.55 9.24,-0.806 8.89,-0.9 8.54,-0.806 8.284,-0.55 8.19,-0.2
  Multi-Layer region: 12.13,-0.9 10.73,-0.9 10.73,0.9 12.13,0.9
  silkscreen extent -12.67,-1.27 12.7,1.17
HDR1X2 [mm]
  rect 1.8x1.8 hole 1: 1(0,0)
  round 1.8 hole 1 slot 1.005 at 0 deg: 2(2.54,0)
  silkscreen extent -1.27,-1.27 3.81,1.27
"HDR1X4 - TOP" [mm]
  rect 1.5x1.5 smd: 1(0,0)
  round 1.5 smd: 2(-2.54,0) 3(-5.08,0) 4(-7.62,0)
HDR2X3 [mm]
  rect 1.6x1.6 hole 1 slot 1.005 at 0 deg: 1(0,0)
  round 1.6 hole 1 slot 1.005 at 0 deg: 2(0,2.54) 3(2.54,0) 4(2.54,2.54) 5(5.08,0) 6(5.08,2.54)
  silkscreen extent -1.27,-1.27 6.35,3.81
HDR2X4 [mm]
  rect 1.8x1.8 hole 1 slot 1.005 at 0 deg: 1(0,0)
  round 1.8 hole 1 slot 1.005 at 0 deg: 2(0,2.54) 3(2.54,0) 4(2.54,2.54) 5(5.08,0) 6(5.08,2.54) 7(7.62,0) 8(7.62,2.54)
  silkscreen extent -1.27,-1.27 8.89,3.81
HDR2X5 [mm]
  rect 1.5x1.5 hole 0.9: 1(0,0)
  round 1.5 hole 0.9: 2(0,2.54) 3(2.54,0) 4(2.54,2.54) 5(5.08,0) 6(5.08,2.54) 7(7.62,0) 8(7.62,2.54) 9(10.16,0) 10(10.16,2.54)
  silkscreen extent -1.27,-1.27 11.43,3.81
HDR-M-2.54_1X5 [mil]
  rect 62x62 hole 35: 1(-200,0)
  round 62 hole 35: 2(-100,0) 3(0,0) 4(100,0) 5(200,0)
  silkscreen extent -250,-50 250,50
HDR_2.54_2X36 [mm]
  round 1.8 hole 1.1: 1(-44.45,-1.27) 2(-44.45,1.27) 3(-41.91,-1.27) 4(-41.91,1.27) 5(-39.37,-1.27) 6(-39.37,1.27) 7(-36.83,-1.27) 8(-36.83,1.27) 9(-34.29,-1.27) 10(-34.29,1.27) 11(-31.75,-1.27) 12(-31.75,1.27) 13(-29.21,-1.27) 14(-29.21,1.27) 15(-26.67,-1.27) 16(-26.67,1.27) 17(-24.13,-1.27) 18(-24.13,1.27) 19(-21.59,-1.27) 20(-21.59,1.27) 21(-19.05,-1.27) 22(-19.05,1.27) 23(-16.51,-1.27) 24(-16.51,1.27) 25(-13.97,-1.27) 26(-13.97,1.27) 27(-11.43,-1.27) 28(-11.43,1.27) 29(-8.89,-1.27) 30(-8.89,1.27) 31(-6.35,-1.27) 32(-6.35,1.27) 33(-3.81,-1.27) 34(-3.81,1.27) 35(-1.27,-1.27) 36(-1.27,1.27) 37(1.27,-1.27) 38(1.27,1.27) 39(3.81,-1.27) 40(3.81,1.27) 41(6.35,-1.27) 42(6.35,1.27) 43(8.89,-1.27) 44(8.89,1.27) 45(11.43,-1.27) 46(11.43,1.27) 47(13.97,-1.27) 48(13.97,1.27) 49(16.51,-1.27) 50(16.51,1.27) 51(19.05,-1.27) 52(19.05,1.27) 53(21.59,-1.27) 54(21.59,1.27) 55(24.13,-1.27) 56(24.13,1.27) 57(26.67,-1.27) 58(26.67,1.27) 59(29.21,-1.27) 60(29.21,1.27) 61(31.75,-1.27) 62(31.75,1.27) 63(34.29,-1.27) 64(34.29,1.27) 65(36.83,-1.27) 66(36.83,1.27) 67(39.37,-1.27) 68(39.37,1.27) 69(41.91,-1.27) 70(41.91,1.27) 71(44.45,-1.27) 72(44.45,1.27)
  silkscreen extent -45.72,-2.54 45.72,2.54
"HEADER 1X2" [mm]
  rect 1.8x1.8 hole 1 slot 1.005 at 0 deg: 1(0,0)
  round 1.8 hole 1 slot 1.005 at 0 deg: 2(2.54,0)
  silkscreen extent -1.27,-1.27 3.81,1.27
"HEADER 1X3" [mm]
  rect 1.8x1.8 hole 1 slot 1.005 at 0 deg: 1(0,0)
  round 1.8 hole 1 slot 1.005 at 0 deg copper offset 0,0: 2(2.54,0) 3(5.08,0)
  silkscreen extent -1.27,-1.27 6.35,1.27
IMPORTED_IMAGE [mil]
LED0603 [mil]
  rect 36x32 smd: 1(-0.04,0.2) 2(60.96,0.2)
  silkscreen extent -28,-28 110,27
"LQFP48 - 2" [mm]
  rect 1.2x0.3 smd: 1(0,0) 2(0,-0.5) 3(0,-1) 4(0,-1.5) 5(0,-2) 6(0,-2.5) 7(0,-3) 8(0,-3.5) 9(0,-4) 10(0,-4.5) 11(0,-5) 12(0,-5.5) 25(8.5,-5.5) 26(8.5,-5) 27(8.5,-4.5) 28(8.5,-4) 29(8.5,-3.5) 30(8.5,-3) 31(8.5,-2.5) 32(8.5,-2) 33(8.5,-1.5) 34(8.5,-1) 35(8.5,-0.5) 36(8.5,0)
  rect 0.3x1.2 smd: 13(1.5,-7) 14(2,-7) 15(2.5,-7) 16(3,-7) 17(3.5,-7) 18(4,-7) 19(4.5,-7) 20(5,-7) 21(5.5,-7) 22(6,-7) 23(6.5,-7) 24(7,-7) 37(7,1.5) 38(6.5,1.5) 39(6,1.5) 40(5.5,1.5) 41(5,1.5) 42(4.5,1.5) 43(4,1.5) 44(3.5,1.5) 45(3,1.5) 46(2.5,1.5) 47(2,1.5) 48(1.5,1.5)
  silkscreen extent -0.12,-5.71 7.11,0.89
LQFP48_7*7 [mm]
  rect 1.2x0.3 smd: 1(-4.25,2.75) 2(-4.25,2.25) 3(-4.25,1.75) 4(-4.25,1.25) 5(-4.25,0.75) 6(-4.25,0.25) 7(-4.25,-0.25) 8(-4.25,-0.75) 9(-4.25,-1.25) 10(-4.25,-1.75) 11(-4.25,-2.25) 12(-4.25,-2.75) 25(4.25,-2.75) 26(4.25,-2.25) 27(4.25,-1.75) 28(4.25,-1.25) 29(4.25,-0.75) 30(4.25,-0.25) 31(4.25,0.25) 32(4.25,0.75) 33(4.25,1.25) 34(4.25,1.75) 35(4.25,2.25) 36(4.25,2.75)
  rect 0.3x1.2 smd: 13(-2.75,-4.25) 14(-2.25,-4.25) 15(-1.75,-4.25) 16(-1.25,-4.25) 17(-0.75,-4.25) 18(-0.25,-4.25) 19(0.25,-4.25) 20(0.75,-4.25) 21(1.25,-4.25) 22(1.75,-4.25) 23(2.25,-4.25) 24(2.75,-4.25) 37(2.75,4.25) 38(2.25,4.25) 39(1.75,4.25) 40(1.25,4.25) 41(0.75,4.25) 42(0.25,4.25) 43(-0.25,4.25) 44(-0.75,4.25) 45(-1.25,4.25) 46(-1.75,4.25) 47(-2.25,4.25) 48(-2.75,4.25)
  silkscreen extent -4.37,-2.96 2.86,3.64
LQFP144_20*20 [mm]
  rect 1.35x0.3 smd: 1(-10.625,8.75) 2(-10.625,8.25) 3(-10.625,7.75) 4(-10.625,7.25) 5(-10.625,6.75) 6(-10.625,6.25) 7(-10.625,5.75) 8(-10.625,5.25) 9(-10.625,4.75) 10(-10.625,4.25) 11(-10.625,3.75) 12(-10.625,3.25) 13(-10.625,2.75) 14(-10.625,2.25) 15(-10.625,1.75) 16(-10.625,1.25) 17(-10.625,0.75) 18(-10.625,0.25) 19(-10.625,-0.25) 20(-10.625,-0.75) 21(-10.625,-1.25) 22(-10.625,-1.75) 23(-10.625,-2.25) 24(-10.625,-2.75) 25(-10.625,-3.25) 26(-10.625,-3.75) 27(-10.625,-4.25) 28(-10.625,-4.75) 29(-10.625,-5.25) 30(-10.625,-5.75) 31(-10.625,-6.25) 32(-10.625,-6.75) 33(-10.625,-7.25) 34(-10.625,-7.75) 35(-10.625,-8.25) 36(-10.625,-8.75) 73(10.625,-8.75) 74(10.625,-8.25) 75(10.625,-7.75) 76(10.625,-7.25) 77(10.625,-6.75) 78(10.625,-6.25) 79(10.625,-5.75) 80(10.625,-5.25) 81(10.625,-4.75) 82(10.625,-4.25) 83(10.625,-3.75) 84(10.625,-3.25) 85(10.625,-2.75) 86(10.625,-2.25) 87(10.625,-1.75) 88(10.625,-1.25) 89(10.625,-0.75) 90(10.625,-0.25) 91(10.625,0.25) 92(10.625,0.75) 93(10.625,1.25) 94(10.625,1.75) 95(10.625,2.25) 96(10.625,2.75) 97(10.625,3.25) 98(10.625,3.75) 99(10.625,4.25) 100(10.625,4.75) 101(10.625,5.25) 102(10.625,5.75) 103(10.625,6.25) 104(10.625,6.75) 105(10.625,7.25) 106(10.625,7.75) 107(10.625,8.25) 108(10.625,8.75)
  rect 0.3x1.35 smd: 37(-8.75,-10.625) 38(-8.25,-10.625) 39(-7.75,-10.625) 40(-7.25,-10.625) 41(-6.75,-10.625) 42(-6.25,-10.625) 43(-5.75,-10.625) 44(-5.25,-10.625) 45(-4.75,-10.625) 46(-4.25,-10.625) 47(-3.75,-10.625) 48(-3.25,-10.625) 49(-2.75,-10.625) 50(-2.25,-10.625) 51(-1.75,-10.625) 52(-1.25,-10.625) 53(-0.75,-10.625) 54(-0.25,-10.625) 55(0.25,-10.625) 56(0.75,-10.625) 57(1.25,-10.625) 58(1.75,-10.625) 59(2.25,-10.625) 60(2.75,-10.625) 61(3.25,-10.625) 62(3.75,-10.625) 63(4.25,-10.625) 64(4.75,-10.625) 65(5.25,-10.625) 66(5.75,-10.625) 67(6.25,-10.625) 68(6.75,-10.625) 69(7.25,-10.625) 70(7.75,-10.625) 71(8.25,-10.625) 72(8.75,-10.625) 109(8.75,10.625) 110(8.25,10.625) 111(7.75,10.625) 112(7.25,10.625) 113(6.75,10.625) 114(6.25,10.625) 115(5.75,10.625) 116(5.25,10.625) 117(4.75,10.625) 118(4.25,10.625) 119(3.75,10.625) 120(3.25,10.625) 121(2.75,10.625) 122(2.25,10.625) 123(1.75,10.625) 124(1.25,10.625) 125(0.75,10.625) 126(0.25,10.625) 127(-0.25,10.625) 128(-0.75,10.625) 129(-1.25,10.625) 130(-1.75,10.625) 131(-2.25,10.625) 132(-2.75,10.625) 133(-3.25,10.625) 134(-3.75,10.625) 135(-4.25,10.625) 136(-4.75,10.625) 137(-5.25,10.625) 138(-5.75,10.625) 139(-6.25,10.625) 140(-6.75,10.625) 141(-7.25,10.625) 142(-7.75,10.625) 143(-8.25,10.625) 144(-8.75,10.625)
  silkscreen extent -10.75,-8.78 8.68,9.89
OSC-SMD_4P-L5.0-W3.2-BL [mm]
  rect 2x1.4 smd: 1(-2.05,-1.2) 2(2.05,-1.2) 3(2.05,1.2) 4(-2.05,1.2)
  silkscreen extent -3.46,-2.26 3.24,2.03
POWERDI-123_L2.8-W1.8-LS3.7-RD [mm]
  rect 2.4x1.5 smd: 1(-1.187,0)
  rect 1.05x1.5 smd: 2(1.187,0)
  silkscreen extent -2,-1 1.2,1
R0603 [mil]
  rect 31.75x34.02 smd: 1(-29.66,0) 2(29.66,0)
  silkscreen extent -55,-26 55,26
RJ45-TH_HR911105A [mm]
  rect 1.6x1.6 hole 1: 1(-4.45,4.355)
  round 1.6 hole 1: 2(-3.18,6.895) 3(-1.91,4.355) 4(-0.64,6.895) 5(0.63,4.355) 6(1.9,6.895) 7(3.17,4.355) 8(4.44,6.895)
  round 1.8 hole 1.1: 9(-6.625,-6.895) 10(-4.085,-6.895) 11(4.085,-6.895) 12(6.625,-6.895)
  round 2.5 hole 1.8: SH1(-7.745,1.055) SH2(7.745,1.055)
  Multi-Layer board cut-out: -7.365,-1.995 -7.202,-2.711 -6.744,-3.285 -6.082,-3.604 -5.348,-3.604 -4.686,-3.285 -4.228,-2.711 -4.065,-1.995 -4.065,-1.995 -4.228,-1.279 -4.686,-0.705 -5.348,-0.386 -6.082,-0.386 -6.744,-0.705 -7.202,-1.279 -7.365,-1.995
  Multi-Layer board cut-out: 4.065,-1.995 4.228,-2.711 4.686,-3.285 5.348,-3.604 6.082,-3.604 6.744,-3.285 7.202,-2.711 7.365,-1.995 7.365,-1.995 7.202,-1.279 6.744,-0.705 6.082,-0.386 5.348,-0.386 4.686,-0.705 4.228,-1.279 4.065,-1.995
  silkscreen extent -8.05,-12.92 8.05,8.68
SB-PAD [mil]
  Top Layer region: -47.24,-19.68 -47.24,19.69 -16.45,19.68 1,0 -17.05,-19.68
  Top Layer region: -4.69,19.68 15,0 -4.69,-19.69 47.24,-19.68 47.24,19.69
  silkscreen extent -50,-23 50,23
SOD-123_L2.8-W1.8-LS3.7-RD [mm]
  rect 0.95x1.15 smd: 1(-1.692,0) 2(1.692,0)
  silkscreen extent -1.63,-0.94 1.41,0.94
SOIC-8_208MIL [mm]
  oval 0.7x2.2 smd: 1(-1.905,-3.4) 2(-0.635,-3.4) 3(0.635,-3.4) 4(1.905,-3.4) 5(1.905,3.4) 6(0.635,3.4) 7(-0.635,3.4) 8(-1.905,3.4)
  silkscreen extent -2.95,-3.9 2.5,1.9
SOT-23-3_L2.9-W1.3-P1.90-LS2.4-BR [mm]
  rect 1.25x0.7 smd: 1(1,-0.95) 2(1,0.95) 3(-1,0)
  silkscreen extent -0.73,-1.53 0.73,1.53
SOT-23-5 [mil]
  rect 50x20 smd: 1(-65,100) 2(-65,63) 3(-65,25) 4(35,25) 5(35,100)
  silkscreen extent -65,1 18,135
SW-SMD_4P-L6.0-W6.0-P4.50-LS9.0 [mm]
  rect 2.2x1.5 smd: 1(-4.4,2.25) 2(-4.4,-2.25) 3(4.4,2.25) 4(4.4,-2.25)
  silkscreen extent -3,-3 3,3
TESTHOOK [mm]
  rect 2.3x2.3 hole 1.2 slot 1.6 at 0 deg: 1(0,0)
  silkscreen extent -1.8,-1.8 1.8,1.8
USB-A-TH__USB-AF-90 [mm]
  round 1.7 hole 1.1 copper offset 0,0: 1(-3.5,1.355) 2(-1,1.355) 3(1,1.355) 4(3.5,1.355)
  round 3.1 hole 2.1: SH1(7,-1.355) SH2(-7,-1.355)
  silkscreen extent -7.22,-11.51 7.22,2.49
USB_MIC_DIP [mm]
  rect 2x0.4 smd: 1(0,-1.3) 2(0,-0.65) 3(0,0) 4(0,0.65) 5(0,1.3)
  oval 2x1.8 hole 0.45 slot 1.2 at 0 deg: 6(-0.495,-3.6) 7(2.975,-3.6) 8(2.975,3.6) 9(-0.495,3.6)
  round 0.5 hole 0.55 unplated: MH1(0.825,2) MH2(0.825,-2)
  silkscreen extent -1.82,-3.6 5.13,3.6

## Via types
v1: diameter 19.69, hole 7.87, Top Layer to Bottom Layer, 1002 vias
v2: diameter 23.62, hole 11.81, Top Layer to Bottom Layer, 48 vias
v3: diameter 24, hole 12, Top Layer to Bottom Layer, 18 vias
v4: diameter 19.68, hole 7.87, Top Layer to Bottom Layer, 16 vias
v5: diameter 35.43, hole 19.69, Top Layer to Bottom Layer, 12 vias
v6: diameter 27.56, hole 15.75, Top Layer to Bottom Layer, 2 vias
v7: diameter 35.43, hole 19.68, Top Layer to Bottom Layer, 2 vias

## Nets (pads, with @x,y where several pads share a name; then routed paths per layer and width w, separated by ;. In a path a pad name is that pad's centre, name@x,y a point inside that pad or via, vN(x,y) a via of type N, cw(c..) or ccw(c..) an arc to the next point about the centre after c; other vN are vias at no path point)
3V3: C13.1 CN4.1 CN7.1 D1.1 D4.1 D5.1 J4.2 J4.4 JP3.1 L3.1 R10.1 R17.1 R26.1 R27.1 R28.1 U8.8 | length 14304.1
  Top Layer w10: R10.1@8285.3,5191.36 8333.7,5191.36 8378.8,5146.36 R17.1@8490.3,5146.36
  Top Layer w15: CN4.1@8142.77,4527.36 8190,4479.86 8398.8,4478.56 8467.2,4546.77 8615.7,4546.77 8615.7,4512.36 v3(8616.26,4511.77) U8.8@8615.7,4423.06
  Top Layer w20: v5(7253.97,3609.01) 7206,3657.07 7206,5038.36 7288.4,5120.77 D5.1@7288.4,5163.56 ; v5(7717.75,3538.36) 7717.8,3686.26 7762.9,3731.36 7937.8,3731.36 v5(8007.75,3801.36) ; v5(8007.75,3801.36) 8641.76,3801.35 8671.76,3831.35 v5(9607.75,3831.36) ; D1.1@8489.7,5372.56 JP3.1@8489.75,5234.36 8489.7,5146.86 R17.1@8490.3,5146.36
  Bottom Layer w15: v3(8616.26,4511.77) 8674.9,4570.47 R28.1@8674.9,4885.66
  Bottom Layer w20: v5(7253.97,3609.01) 7324.6,3538.36 v5(7717.75,3538.36) 7771.6,3484.57 7771.6,3349.26 7718.2,3295.97 7705,3282.66 CN7.1@7705,3165.97 ; v5(8007.75,3801.36) 8007.8,5165.36 8076.8,5234.36 JP3.1@8489.75,5234.36 8489.7,5429.36 8388.8,5530.36 8388.8,5845.86 8491.7,5948.77 11984.82,5948.77 12164.8,5768.88 12164.8,5467.36 12074.4,5377.06 L3.1@12074.4,5091.36 ; 8007.8,4505.26 8027.1,4524.56 8027.1,4527.97 ; 8007.8,4547.27 8027.1,4527.97 ; CN4.1@8142.77,4527.36 8027.1,4527.97 ; v5(9607.75,3831.36) 9898.8,3831.36 9949.4,3780.76 J4.2@9949.36,3565.36 ; 9949.4,3638.16 9967.1,3656.36 ; 9949.4,3674.07 9967.1,3656.36 ; J4.4@10149.36,3565.36 10149.4,3618.76 10111.8,3656.36 9967.1,3656.36
3V3_EMAC: C41.1 C42.1 C43.1 C44.1 CN5.9 CN5.12 L3.2 R66.1 R67.1 R68.1 R69.1 R72.2 R75.2 U4.23 U4.30 U4.31 U4.41 | length 3497.7
  Top Layer w6: v4(11970.38,5169.76) 12108.68,5169.76 v4(12112.22,5173.3) ; v3@12111.48,5352.58 12153.98,5352.58 R68.1@12155.7,5350.86
  Top Layer w10: U4.31@12144.43,4963.52 12213.8,4963.47 v3(12213.75,4983.35) 12144.6,4983.36 U4.30@12144.43,4983.19 ; v3(12223.17,5094.35) U4.23@12223.17,5140.68 ; U4.41@12282.2,4806.06 12282.2,4860.36 v3(12283.25,4861.35)
  Top Layer w15: CN5.12@12576.92,5788.81 12649.47,5861.35 13026.04,5861.35 CN5.9@13098.63,5788.77
  Bottom Layer w6: R72.2@11949,5122.08 11949,4937.3 R69.1@11951.75,4934.54 ; R72.2@11949,5123.66 11949,5148.37 v4(11970.38,5169.76) ; v3@12111.48,5352.58 12110.65,5351.75 12110.65,5174.88 v4(12112.22,5173.3) 12135.1,5150.43 L3.2@12135.12,5091.36
  Bottom Layer w10: v3(12223.17,5094.35) v3@12223.3,5094.27
  Bottom Layer w15: L3.2@12135.12,5091.36 12134.2,5034.36 12134.2,4982.36 12212.8,4982.36 v3(12213.75,4983.35) ; v3@12206.33,4982.44 12223.17,4998.81 ; v3(12283.25,4861.35) 12283.3,4968.42 ; CN5.12@12576.9,5788.77 12574.5,5786.36 12427.8,5786.36 12223.3,5581.86 C43.1@12223.26,5049.36 12223.3,4999.68 ; R75.2@12650.3,5069.36 12650.3,5011.86 12621.8,4983.36 12300.2,4983.36 ; v3(12213.75,4983.35) 12223.3,4992.86 12223.3,4999.68 ; v3(12213.75,4983.35) 12239.94,4983.36 ; 12223.3,4999.68 12239.94,4983.36 ; 12239.94,4983.36 12265.99,4983.36 ; 12265.99,4983.36 12283.3,4968.42 ; 12265.99,4983.36 12281.8,4983.36 ; 12281.8,4983.36 12283.3,4981.86 12283.3,4968.56 ; 12281.8,4983.36 12300.2,4983.36 ; 12283.3,4968.42 12283.3,4968.56 ; 12283.3,4968.56 12300.2,4983.36
  other v3: 12111.43,5352.57
5V: CN1.1 CN4.2 CN7.2 D2.1 D3.1 D6.1 F1.1 J4.5 J7.2 Q1.2 Q2.2 R33.2 R36.2 | length 12402.1
  Top Layer w10: R36.2@12626.7,3188.07 12628.7,3186.16 Q2.2@12699.33,3186.16
  Top Layer w30: v5(7671.2,3475.57) 7671.2,3694.36 7749.7,3772.86 7917.9,3772.86 7960.7,3815.66 v5@7960.7,3973.36 ; v5(7960.75,3973.36) v5(8287.75,3973.36) ; v5(7961.75,4594.35) 8175.78,4594.35 CN4.2@8242.77,4527.36 ; v5(7985.75,5297.35) F1.1@7985.8,5399.36 ; J7.2@11364.4,4665.97 11419.04,4665.97 11538.99,4546.02 11798.24,4546.02 12083.07,4261.19 12732.9,4261.19 CN1.1@12733.78,4262.08 ; R33.2@12558,3758.36 12558.7,3758.97 Q1.2@12653.23,3758.97 ; v5(12695.74,3593.36) D6.1@12804.22,3592.97 D2.1@12804.2,3686.76 ; v5@12697.7,3134.76 12697.7,3184.57 Q2.2@12699.33,3186.16
  Bottom Layer w15: D3.1@7615.2,3325.76 7615.2,3261.57 7653.2,3223.57 7653.2,3117.76 CN7.2@7705,3065.97 ; 10088.8,3104.36 10088.8,3404.36 10090.8,3406.36
  Bottom Layer w30: D3.1@7615.2,3325.76 7651.4,3325.76 7671.2,3345.57 v5(7671.2,3475.57) ; v5(7960.75,3973.36) 7960.75,5272.36 v5(7985.75,5297.35) ; v5(8287.75,3973.36) 8287.8,3169.76 8365.3,3092.16 11990.9,3092.16 12259.2,3360.47 12665.1,3360.47 ; 10090.8,3406.36 J4.5@10249.36,3565.36 ; v5@12606.57,3758.35 12606.57,3682.54 v5(12695.74,3593.36) 12697.7,3593.36 12697.7,3392.76 ; v5@12606.6,3758.36 12606.6,4062.92 12733.79,4190.11 CN1.1@12733.78,4262.08 ; v5@12697.7,3134.76 12697.7,3329.07 ; 12665.1,3360.47 12697.7,3392.76 ; 12665.1,3360.47 12666.3,3360.47 12697.7,3329.07 ; 12697.7,3329.07 12697.7,3392.76
  other v5: 12697.71,3134.74 12606.57,3758.34
$1N184: C15.1 C16.1 C18.1 C19.1 F2.2 U5.1 U5.3 U7.1 U7.3 | length 539.5
  Top Layer w20: U5.3@7309.8,5472.86 7309.8,5551.86 C19.1@7310.8,5552.86 ; U5.1@7384.8,5472.86 C18.1@7384.8,5552.86 ; U7.3@7678.98,5474.91 C15.1@7679,5553.06 ; U7.1@7753.98,5474.91 C16.1@7754,5554.86
  Top Layer w30: C19.1@7310.8,5552.86 C18.1@7384.8,5552.86 ; F2.2@7607.2,5554.97 7753.9,5554.97 C16.1@7754,5554.86
  other v7: 7413.97,5474.02 7607.97,5476.02
$1N327: R43.1 R49.1 U7.4 | length 163.4
  Top Layer w20: R49.1@7606.6,5303.06 7692.6,5303.06 7692.6,5333.97 7679,5347.56 U7.4@7678.98,5374.91
$1N395: R50.1 R51.1 U5.4 | length 163.5
  Top Layer w20: R51.1@7238.6,5300.06 7323.6,5300.06 7323.6,5328.06 7309.8,5341.77 U5.4@7309.8,5372.86
$1N456: LD1.1 RP1.8 | length 183.7
  Top Layer w6: v2@7600.6,5052.06 LD1.1@7649,5052.06
  Bottom Layer w6: v2@7600.6,5052.06 7655.6,5052.06 7675.4,5071.86 RP1.8@7727.7,5071.86
  other v2: 7600.55,5052.02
